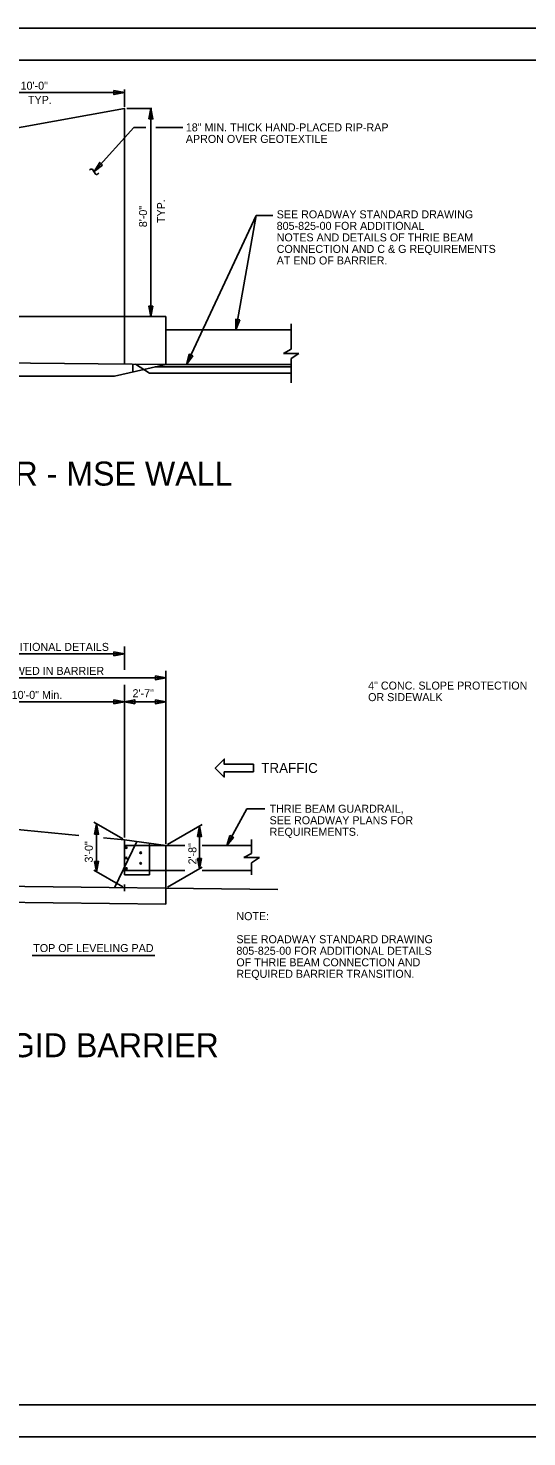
# Model space of a CAD drawing. Extents: x 96 to 240, y 601 to 689.
# Drawn here: x 153.1 to 184.2, y 601 to 689 of the extents above; entities that cross this region are included whole.
import ezdxf

# ---------------------------------------------------------------- set-up
doc = ezdxf.new("R2010")
doc.units = 0
for name, color, linetype in [('BR_AUTO DIMENSION', 7, 'Continuous'), ('BR_BORDER LINES', 7, 'Continuous'), ('BR_CONCRETE', 7, 'Continuous'), ('BR_STRUCTURAL STEEL', 7, 'Continuous'), ('BR_TEXT', 7, 'Continuous'), ('Default', 7, 'Continuous'), ('Level 31', 7, 'Continuous')]:
    doc.layers.add(name, color=color, linetype=linetype)

msp = doc.modelspace()

# ---------------------------------------------------------------- linework, layer by layer
at = {"layer": 'BR_AUTO DIMENSION'}
for p, q in [((148.363, 684.981), (159.066, 684.981)), ((159.066, 684.099), (159.066, 685.177)), ((159.224, 683.99), (160.782, 683.99)), ((160.719, 683.99), (160.719, 670.994)), ((159.658, 682.794), (157.184, 680.055)), ((160.408, 682.794), (159.658, 682.794)), ((162.712, 682.794), (161.024, 682.794)), ((167.284, 677.301), (162.94, 667.994)), ((167.284, 677.301), (166.022, 670.158)), ((168.321, 677.301), (167.284, 677.301)), ((169.464, 670.536), (169.464, 668.956)), ((168.992, 668.69), (169.464, 668.956)), ((169.534, 668.69), (168.992, 668.69)), ((169.464, 668.69), (169.955, 668.69)), ((169.955, 668.69), (169.464, 668.361)), ((169.464, 668.361), (169.464, 666.851)), ((159.066, 648.921), (159.066, 650.384)), ((131.614, 649.919), (159.066, 649.919)), ((161.649, 638.05), (161.649, 648.862)), ((138.644, 648.421), (161.649, 648.421)), ((159.066, 638.449), (159.066, 647.987)), ((138.644, 646.922), (161.649, 646.922)), ((165.453, 637.94), (166.707, 640.233)), ((166.707, 640.233), (167.82, 640.233)), ((158.965, 638.362), (157.158, 639.401)), ((157.333, 636.3), (157.333, 639.301)), ((161.75, 637.998), (163.92, 639.247)), ((163.745, 636.48), (163.745, 639.147)), ((167, 638.317), (167, 637.454)), ((166.528, 637.187), (167, 637.454)), ((167.07, 637.187), (166.528, 637.187)), ((167, 637.187), (167.491, 637.187)), ((167.491, 637.187), (167, 636.858)), ((158.965, 635.361), (157.158, 636.401)), ((161.75, 635.332), (163.92, 636.581)), ((167, 636.858), (167, 636.104)), ((159.066, 635.088), (159.066, 635.5)), ((153.313, 631.076), (160.975, 631.076))]:
    msp.add_line(p, q, dxfattribs=at)
for points in [[(158.416, 685.106), (159.066, 684.981), (158.416, 684.856)], [(160.594, 683.34), (160.719, 683.99), (160.844, 683.34)], [(157.712, 680.454), (157.184, 680.055), (157.527, 680.622)], [(160.844, 671.644), (160.719, 670.994), (160.594, 671.644)], [(166.26, 670.776), (166.022, 670.158), (166.014, 670.82)], [(163.328, 668.531), (162.94, 667.994), (163.102, 668.636)], [(158.416, 650.044), (159.066, 649.919), (158.416, 649.794)], [(160.999, 648.546), (161.649, 648.421), (160.999, 648.296)], [(158.416, 647.047), (159.066, 646.922), (158.416, 646.797)], [(159.716, 646.797), (159.066, 646.922), (159.716, 647.047)], [(160.999, 647.047), (161.649, 646.922), (160.999, 646.797)], [(167.119, 642.546), (167.119, 643.023), (165.3, 643.023), (165.3, 643.346), (164.738, 642.784), (165.3, 642.223), (165.3, 642.546)], [(157.208, 638.651), (157.333, 639.301), (157.458, 638.651)], [(163.62, 638.497), (163.745, 639.147), (163.87, 638.497)], [(165.655, 638.571), (165.453, 637.94), (165.874, 638.451)], [(163.62, 637.13), (163.745, 636.48), (163.87, 637.13)], [(157.208, 636.95), (157.333, 636.3), (157.458, 636.95)]]:
    msp.add_lwpolyline(points, close=True, dxfattribs=at)
at = {"layer": 'BR_BORDER LINES'}
for p, q in [((237.837, 687.003), (103.173, 687.003)), ((103.173, 603.003), (237.837, 603.003))]:
    msp.add_line(p, q, dxfattribs=at)
at = {"layer": 'BR_CONCRETE'}
for p, q in [((115.181, 670.994), (161.649, 670.994)), ((159.066, 668.021), (159.066, 670.994)), ((161.649, 667.994), (161.649, 670.994)), ((161.649, 667.994), (138.644, 668.232)), ((158.46, 667.262), (161.649, 667.994)), ((115.181, 667.262), (158.46, 667.262)), ((156.23, 638.573), (150.794, 639.088)), ((159.066, 638.304), (157.763, 638.427)), ((159.847, 638.194), (158.46, 635.31)), ((159.066, 638.304), (161.649, 637.94)), ((161.649, 637.94), (161.649, 634.273)), ((161.649, 634.273), (115.181, 634.81))]:
    msp.add_line(p, q, dxfattribs=at)
at = {"layer": 'BR_STRUCTURAL STEEL'}
for p, q in [((161.649, 670.158), (169.464, 670.158)), ((159.598, 668.016), (159.598, 667.523)), ((160.631, 667.447), (159.759, 668.014)), ((161.649, 667.994), (169.464, 667.994)), ((160.631, 667.447), (169.464, 667.447)), ((160.99, 667.843), (169.464, 667.843)), ((159.066, 638.304), (159.066, 636.103)), ((160.629, 636.103), (160.629, 638.084)), ((159.066, 637.94), (162.843, 637.94)), ((163.91, 637.94), (167, 637.94)), ((159.066, 636.381), (162.843, 636.381)), ((163.91, 636.381), (167, 636.381)), ((159.066, 636.103), (160.629, 636.103))]:
    msp.add_line(p, q, dxfattribs=at)
for centre in [(159.192, 637.814), (159.192, 637.166), (160.079, 637.49), (159.192, 636.506), (160.079, 636.836)]:
    msp.add_circle(centre, 0.0509, dxfattribs=at)
at = {"layer": 'BR_TEXT'}
for p, q in [((159.066, 670.994), (159.066, 683.99)), ((156.886, 680.129), (156.928, 680.165)), ((157.128, 680.121), (157.237, 679.929)), ((157.414, 679.895), (157.473, 679.94))]:
    msp.add_line(p, q, dxfattribs=at)
msp.add_lwpolyline([(159.066, 670.994), (148.363, 670.994), (148.363, 682.045), (159.066, 683.99)], close=True, dxfattribs=at)
for centre, radius, start, end in [((157.014, 680.073), 0.125, 23.15642, 132.95529), ((157.337, 679.976), 0.111, 205.60127, 313.88685)]:
    msp.add_arc(centre, radius, start, end, dxfattribs=at)
at = {"layer": 'Default'}
msp.add_line((168.631, 635.193), (115.181, 635.81), dxfattribs=at)
at = {"layer": 'Level 31'}
msp.add_line((239.84, 689.004), (95.84, 689.004), dxfattribs=at)
msp.add_lwpolyline([(95.84, 689.004), (95.84, 601.004), (239.84, 601.004), (239.84, 689.004)], dxfattribs=at)

# ---------------------------------------------------------------- texts
at = {"layer": 'BR_AUTO DIMENSION'}
for s, p in [('10\'-0"', (152.593, 685.16)), ('TYP.', (153.053, 684.275)), ('18" MIN. THICK HAND-PLACED RIP-RAP ', (162.9, 682.555)), ('APRON OVER GEOTEXTILE', (162.9, 681.835)), ('SEE ROADWAY STANDARD DRAWING', (168.569, 677.124)), ('805-825-00 FOR ADDITIONAL', (168.569, 676.404)), ('NOTES AND DETAILS OF THRIE BEAM', (168.569, 675.683)), ('CONNECTION AND C & G REQUIREMENTS', (168.569, 674.963)), ('AT END OF BARRIER.', (168.569, 674.242)), ('4" CONC. SLOPE PROTECTION', (174.275, 647.684)), ('OR SIDEWALK', (174.275, 646.964)), ('THRIE BEAM GUARDRAIL,', (168.127, 639.992)), ('SEE ROADWAY PLANS FOR ', (168.127, 639.271)), ('REQUIREMENTS.', (168.127, 638.551)), ('NOTE:', (166.054, 633.28)), ('SEE ROADWAY STANDARD DRAWING', (166.054, 631.839)), ('805-825-00 FOR ADDITIONAL DETAILS', (166.054, 631.119)), ('OF THRIE BEAM CONNECTION AND', (166.054, 630.398)), ('REQUIRED BARRIER TRANSITION.', (166.054, 629.678))]:
    msp.add_text(s, height=0.5, dxfattribs=at).set_placement(p)
for s, height, rotation, p in [('8\'-0"', 0.5, 90, (160.48, 676.57)), ('TYP.', 0.5, 90, (161.6, 676.831)), ('SEE ROADWAY STANDARD DRAWING 805-805-01 FOR ADDITIONAL DETAILS', 0.5, 360, (133.472, 650.102)), ('NO EXPANSION JOINTS ALLOWED IN BARRIER', 0.5, 360, (142.679, 648.604)), ('2\'-7"', 0.5, 360, (159.576, 647.207)), ('10\'-0" Min.', 0.5, 360, (152.036, 647.105)), ('TRAFFIC', 0.625, 360, (167.606, 642.475)), ('3\'-0"', 0.5, 90, (157.096, 636.878)), ('2\'-8"', 0.5, 90, (163.562, 636.762)), ('TOP OF LEVELING PAD', 0.5, 360, (153.381, 631.288))]:
    msp.add_text(s, height=height, rotation=rotation, dxfattribs=at).set_placement(p)
at = {"layer": 'BR_TEXT'}
for s, p in [('PARTIAL PLAN OF RIGID BARRIER - MSE WALL', (120.556, 660.429)), ('PARTIAL ELEVATION OF RIGID BARRIER', (125.836, 624.719))]:
    msp.add_text(s, height=1.5, dxfattribs=at).set_placement(p)

doc.saveas('drawing.dxf')
